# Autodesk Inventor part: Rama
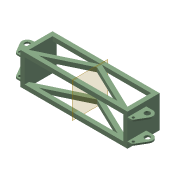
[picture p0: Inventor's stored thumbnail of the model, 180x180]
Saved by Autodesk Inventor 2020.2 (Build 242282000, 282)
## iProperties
Created: 2005-10
Part Number: Rama
Document SubType Name: Modeling
Designer: F.Stasiak
Density: 1 g/cm^3
Material: Ogólny
Appearance: Zielony pastelowy
Manager: www.cadconsulting.pl
Company: Fabian Stasiak CAD Consulting
Author: F.Stasiak
Subject: Zbiór ćwiczeń. Autodesk Inventor 2020. Kurs podstawowy
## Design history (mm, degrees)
sketch "Szkic1"
  geometry: L1 (1000, 600)-(-1000, 600); L2 (-1000, 600)-(-1000, 0); L3 (-1000, 0)-(1000, 0); L4 (1000, 0)-(1000, 600); 2 further points
  constraints: 8 end point, 2 parallel, 1 coincident, 1 horizontal, 1 midpoint, 1 perpendicular
  dimensions: "d0" = 2000 distance of L2.end L3.end; "d1" = 600 distance of L1.end L2.end
extrude "Wyciągnięcie proste1" new body sketch "Szkic1" stored distance "d2" = 600; taper "d3" = 0 deg
node "Płaszczyzna konstrukcyjna1"
feature "Skorupa1" dims "d17" = 80
sketch "Szkic3"
  geometry: L1 (1000, 600)-(1000, 0) reference; L2 (-1000, 600)-(1000, 600) reference; L3 (-1000, 0)-(-1000, 600) reference; L4 (1000, 0)-(-1000, 0) reference; L5 (920, 520)-(920, 80); L6 (920, 80)-(-920, 80); L7 (-920, 80)-(-920, 520); L8 (-920, 520)-(920, 520); L9 (-920, 80)-(0, 520); L10 (920, 80)-(0, 520); L11 (-734.581, 80)-(0, 431.321); L12 (0, 431.321)-(734.581, 80)
  constraints: 16 end point, 2 point on line, 1 midpoint, 3 other
  dimensions: "d18" = 80 distance between parallel lines of L2 L8; "d19" = 80 distance between parallel lines of L11 L9 (= d18)
extrude "Wyciągnięcie proste3" cut sketch "Szkic3" extent not by distance; stored distance "d20" = 10; taper "d21" = 0 deg
sketch "Szkic2"
  geometry: L1 (-1000, 0)-(-1000, 600) reference; L2 (-1120, 350)-(-1000, 350); L3 (-1000, 350)-(-1000, 0); L4 (-1000, 0)-(-1060, 0); L5 (-1103.058, 24.583)-(-1206.115, 199.165); C1 r 50 at (-1120, 250); C2 r 25 at (-1060, 50); A1 r 100 centre (-1120, 250) between (-1120, 350) and (-1206.115, 199.165); A2 r 50 centre (-1060, 50) between (-1103.058, 24.583) and (-1060, 0)
  constraints: 8 end point, 4 centre point, 4 point on circle, 4 tangent, 2 coincident, 1 collinear, 1 horizontal, 1 perpendicular, 1 point on line
  dimensions: "d5" = 100 radius of A1; "d8" = 100 diameter of C1; "d12" = 350 distance of L2.end L1.start; "d13" = 120 distance from line of L1 A1.centre; "d14" = 50 radius of A2; "d15" = 60 distance of L1.start L4.end; "d16" = 50 diameter of C2
extrude "Wyciągnięcie proste2" join sketch "Szkic2" distance "d9" = 30; taper "d10" = 0 deg
mirror "Lustro1"
mirror "Lustro2"
node "Bryła1"
node "Korpusy bryłowe"
node "Korpusy powierzchniowe"
node "Pętla rzutowana1"
